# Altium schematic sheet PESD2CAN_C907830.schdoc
size 127 x 101 mm
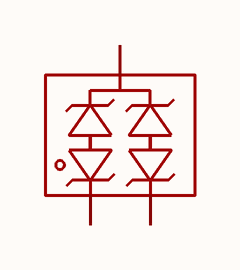
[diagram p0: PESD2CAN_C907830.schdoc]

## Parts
D?  pesd2can_c907830  [SOT-23-3_L2.9-W1.3-P1.90-LS2.4-BR]  (value not drawn)

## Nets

Not connected (* = marked no-connect by the designer): D? 1 2 3

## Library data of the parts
D? = pesd2can_c907830: 极性:双向;反向截止电压(Vrwm):24V;钳位电压:50V;峰值脉冲电流(Ipp):5.5A@8/20us;峰值脉冲功率(Ppp):250W@8/20us;击穿电压:32V;; Manufacturer: TECH PUBLIC(台舟); AddInBom: yes; ModelId: c62791f0466c4ae2a892c056b845b0ca; ModelName: SOT-23-3P_L2.9-W1.3-H1.0-LS2.4-P0.95; ModelTransform: 98.425,114.173,0,180,0,0,0.0005,-0.0005,0; Polarity: 双向; Reverse Stand-Off Voltage (Vrwm): 24V; Clamping Voltage: 50V; Voltage - Breakdown: 32V; Reverse Leakage Current (Ir): 80nA; Number of Channels: 双路; level of protection: IEC 61000-4-2；IEC 61000-4-4；IEC 61000-4-5; Type: ESD; Junction Capacitance: 17pF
